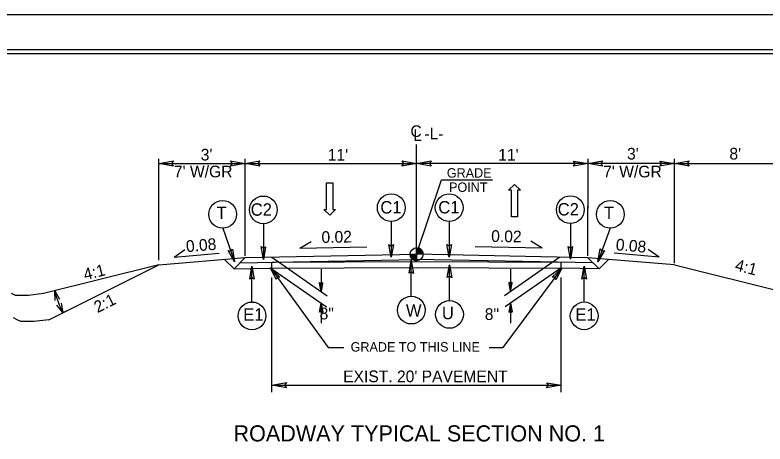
# Model space of a CAD drawing. Extents: x 573711 to 575883, y -54585 to -53485.
# Drawn here: x 574438.9 to 574921.1, y -53761 to -53485 of the extents above; entities that cross this region are included whole.
import ezdxf

# ---------------------------------------------------------------- set-up
doc = ezdxf.new("R2010")
doc.units = 0
for name, color, linetype in [('Old_Level_1', 7, 'Continuous'), ('Old_Level_11', 7, 'Continuous'), ('Old_Level_2', 7, 'Continuous'), ('Old_Level_20', 7, 'Continuous'), ('Old_Level_3', 7, 'Continuous'), ('Prop Lane Arrow CELL', 7, 'Continuous'), ('Prop Terminator CELL', 7, 'Continuous'), ('Sheet Cutting Line CELL', 7, 'Continuous'), ('Sheet Plot Border Inside CELL', 7, 'Continuous'), ('Sheet Plot Border Outside CELL', 7, 'Continuous'), ('Sheet Typical CELL', 7, 'Continuous'), ('Typical Terminator CELL', 7, 'Continuous')]:
    doc.layers.add(name, color=color, linetype=linetype)

msp = doc.modelspace()

# ---------------------------------------------------------------- linework, layer by layer
at = {"layer": 'Old_Level_1'}
for p, q in [((574697.08, -53638.91), (574697.09, -53568.35)), ((574697.08, -53638.91), (574697.08, -53634.76)), ((574531.29, -53645.73), (574586.89, -53641.11)), ((574573.62, -53642.21), (574579.7, -53648.29)), ((574579.7, -53648.29), (574586.89, -53641.11)), ((574583.5, -53644.49), (574697.08, -53642.22)), ((574586.89, -53641.11), (574697.08, -53638.91)), ((574604.04, -53640.76), (574639.68, -53665.73)), ((574692.94, -53638.91), (574697.08, -53638.91)), ((574697.07, -53643.06), (574697.08, -53638.91)), ((574697.08, -53638.91), (574697.07, -53643.06)), ((574807.28, -53641.13), (574697.08, -53638.91)), ((574701.23, -53638.91), (574697.08, -53638.91)), ((574810.66, -53644.51), (574697.08, -53642.23)), ((574789.14, -53640.76), (574753.5, -53665.73)), ((574807.28, -53641.13), (574814.46, -53648.31)), ((574862.87, -53645.76), (574807.28, -53641.13)), ((574814.46, -53648.31), (574820.54, -53642.23)), ((574531.29, -53645.73), (574457.17, -53664.25)), ((574460.68, -53681.03), (574531.29, -53645.73)), ((574604.04, -53644.08), (574697.08, -53643.68)), ((574604.04, -53647.8), (574604.04, -53644.08)), ((574604.04, -53647.8), (574697.08, -53647.4)), ((574697.08, -53643.68), (574790.14, -53644.1)), ((574697.08, -53647.4), (574790.14, -53647.82)), ((574790.14, -53647.82), (574790.14, -53644.1)), ((574862.87, -53645.76), (574936.99, -53664.3)), ((574579.7, -53648.29), (574604.04, -53647.8)), ((574603.43, -53647.82), (574639.07, -53672.77)), ((574635.69, -53648.49), (574635.69, -53662.93)), ((574789.74, -53647.82), (574754.11, -53672.77)), ((574757.48, -53648.49), (574757.48, -53662.93)), ((574814.46, -53648.31), (574790.14, -53647.82)), ((574635.69, -53662.93), (574634.72, -53657.41)), ((574635.69, -53658.12), (574634.72, -53657.41)), ((574635.69, -53662.93), (574635.41, -53657.92)), ((574635.69, -53662.93), (574636.67, -53657.41)), ((574636.67, -53657.41), (574635.69, -53658.12)), ((574636.52, -53657.51), (574635.69, -53662.93)), ((574757.48, -53662.93), (574756.51, -53657.41)), ((574756.51, -53657.41), (574757.48, -53658.12)), ((574756.66, -53657.51), (574757.48, -53662.93)), ((574757.48, -53662.93), (574758.46, -53657.41)), ((574757.48, -53662.93), (574757.77, -53657.92)), ((574635.69, -53670.41), (574634.72, -53675.93)), ((574635.69, -53670.41), (574635.69, -53683.33)), ((574635.69, -53670.41), (574636.67, -53675.93)), ((574757.49, -53670.41), (574756.51, -53675.93)), ((574757.49, -53670.41), (574757.49, -53683.33)), ((574757.49, -53670.41), (574758.46, -53675.93)), ((574634.72, -53675.93), (574635.69, -53675.22)), ((574635.69, -53675.22), (574636.67, -53675.93)), ((574757.49, -53675.22), (574756.51, -53675.93))]:
    msp.add_line(p, q, dxfattribs=at)
for points in [[(574697.12, -53634.76), (574697.12, -53634.76), (574697.12, -53638.91)], [(574697.2, -53634.76), (574697.2, -53638.91)], [(574697.29, -53634.77), (574697.29, -53638.91)], [(574697.37, -53634.77), (574697.37, -53638.91)], [(574697.45, -53634.78), (574697.45, -53638.91)], [(574697.54, -53634.79), (574697.53, -53638.91)], [(574697.62, -53634.8), (574697.62, -53638.91)], [(574697.7, -53634.81), (574697.7, -53638.91)], [(574697.78, -53634.82), (574697.78, -53638.91)], [(574697.87, -53634.84), (574697.87, -53638.91)], [(574697.95, -53634.86), (574697.95, -53638.91)], [(574698.03, -53634.87), (574698.03, -53638.91)], [(574698.12, -53634.89), (574698.12, -53638.91)], [(574698.2, -53634.92), (574698.2, -53638.91)], [(574698.28, -53634.94), (574698.28, -53638.91)], [(574698.36, -53634.97), (574698.36, -53638.91)], [(574698.45, -53634.99), (574698.45, -53638.91)], [(574698.53, -53635.02), (574698.53, -53638.91)], [(574698.61, -53635.06), (574698.61, -53638.91)], [(574698.7, -53635.1), (574698.7, -53638.91)], [(574698.78, -53635.13), (574698.78, -53638.91)], [(574698.86, -53635.17), (574698.86, -53638.91)], [(574698.95, -53635.21), (574698.95, -53638.91)], [(574699.03, -53635.25), (574699.03, -53638.91)], [(574699.11, -53635.3), (574699.11, -53638.91)], [(574699.19, -53635.34), (574699.19, -53638.91)], [(574699.28, -53635.39), (574699.28, -53638.91)], [(574699.36, -53635.45), (574699.36, -53638.91)], [(574699.44, -53635.5), (574699.44, -53638.91)], [(574699.53, -53635.57), (574699.53, -53638.91)], [(574699.61, -53635.62), (574699.61, -53638.91)], [(574699.69, -53635.69), (574699.69, -53638.91)], [(574699.77, -53635.76), (574699.77, -53638.91)], [(574699.86, -53635.83), (574699.86, -53638.91)], [(574699.94, -53635.91), (574699.94, -53638.91)], [(574700.02, -53635.99), (574700.02, -53638.91)], [(574700.11, -53636.07), (574700.11, -53638.91)], [(574700.19, -53636.17), (574700.19, -53638.91)], [(574700.27, -53636.27), (574700.27, -53638.91)], [(574700.36, -53636.37), (574700.36, -53638.91)], [(574700.44, -53636.48), (574700.44, -53638.91)], [(574700.52, -53636.6), (574700.52, -53638.91)], [(574700.6, -53636.73), (574700.6, -53638.91)], [(574700.69, -53636.87), (574700.69, -53638.91)], [(574700.77, -53637.01), (574700.77, -53638.91)], [(574700.85, -53637.19), (574700.85, -53638.91)], [(574700.94, -53637.38), (574700.94, -53638.91)], [(574701.02, -53637.61), (574701.02, -53638.91)], [(574701.1, -53637.9), (574701.1, -53638.91)], [(574692.95, -53638.91), (574692.95, -53639.36)], [(574693.04, -53638.91), (574693.04, -53639.85)], [(574693.12, -53638.91), (574693.12, -53640.15)], [(574693.2, -53638.91), (574693.2, -53640.4)], [(574693.29, -53638.91), (574693.29, -53640.59)], [(574693.37, -53638.91), (574693.37, -53640.76)], [(574693.45, -53638.91), (574693.45, -53640.92)], [(574693.53, -53638.91), (574693.53, -53641.07)], [(574693.62, -53638.91), (574693.62, -53641.2)], [(574693.7, -53638.91), (574693.7, -53641.32)], [(574693.78, -53638.91), (574693.78, -53641.43)], [(574693.87, -53638.91), (574693.87, -53641.53)], [(574693.95, -53638.91), (574693.95, -53641.63)], [(574694.03, -53638.91), (574694.03, -53641.72)], [(574694.11, -53638.91), (574694.11, -53641.81)], [(574694.2, -53638.91), (574694.2, -53641.9)], [(574694.28, -53638.91), (574694.28, -53641.97)], [(574694.36, -53638.91), (574694.36, -53642.05)], [(574694.45, -53638.91), (574694.45, -53642.12)], [(574694.53, -53638.91), (574694.53, -53642.18)], [(574694.61, -53638.91), (574694.61, -53642.25)], [(574694.7, -53638.91), (574694.7, -53642.3)], [(574694.78, -53638.91), (574694.78, -53642.36)], [(574694.86, -53638.91), (574694.86, -53642.41)], [(574694.94, -53638.91), (574694.94, -53642.47)], [(574695.03, -53638.91), (574695.03, -53642.52)], [(574695.11, -53638.91), (574695.11, -53642.56)], [(574695.19, -53638.91), (574695.19, -53642.61)], [(574695.28, -53638.91), (574695.28, -53642.64)], [(574695.36, -53638.91), (574695.36, -53642.68)], [(574695.44, -53638.91), (574695.44, -53642.72)], [(574695.53, -53638.91), (574695.52, -53642.76)], [(574695.61, -53638.91), (574695.61, -53642.79)], [(574695.69, -53638.91), (574695.69, -53642.82)], [(574695.77, -53638.91), (574695.77, -53642.85)], [(574695.86, -53638.91), (574695.86, -53642.88)], [(574695.94, -53638.91), (574695.94, -53642.89)], [(574696.02, -53638.91), (574696.02, -53642.92)], [(574696.11, -53638.91), (574696.11, -53642.94)], [(574696.19, -53638.91), (574696.19, -53642.96)], [(574696.27, -53638.91), (574696.27, -53642.98)], [(574696.35, -53638.91), (574696.35, -53643)], [(574696.44, -53638.91), (574696.44, -53643)], [(574696.52, -53638.91), (574696.52, -53643.02)], [(574696.6, -53638.91), (574696.6, -53643.03)], [(574696.69, -53638.91), (574696.69, -53643.04)], [(574696.77, -53638.91), (574696.77, -53643.05)], [(574696.85, -53638.91), (574696.85, -53643.05)], [(574696.94, -53638.91), (574696.94, -53643.06)], [(574697.02, -53638.91), (574697.02, -53643.06), (574697.02, -53643.06)], [(574701.19, -53638.32), (574701.18, -53638.91)], [(574457.17, -53664.25), (574447.55, -53665.45), (574445.15, -53665.45), (574441.54, -53665.45), (574439.14, -53665.45), (574436.74, -53664.26)], [(574460.68, -53681.03), (574451.07, -53682.23), (574448.66, -53682.23), (574445.05, -53682.23), (574442.65, -53682.23), (574440.25, -53681.03), (574437.84, -53679.83)]]:
    msp.add_lwpolyline(points, dxfattribs=at)
msp.add_circle((574697.08, -53638.91), 4.15, dxfattribs=at)
for start, end in [(359.9851, 89.9851), (179.9851, 269.9851)]:
    msp.add_arc((574697.08, -53638.91), 4.15, start, end, dxfattribs=at)
at = {"layer": 'Old_Level_11'}
for p, q in [((574531.29, -53642.73), (574531.3, -53577.53)), ((574531.29, -53642.73), (574531.3, -53577.53)), ((574586.89, -53638.1), (574586.89, -53577.54)), ((574586.89, -53638.1), (574586.89, -53577.54)), ((574586.89, -53639.9), (574586.89, -53578.86)), ((574807.28, -53638.13), (574807.29, -53577.56)), ((574807.28, -53638.13), (574807.29, -53577.56)), ((574807.28, -53639.92), (574807.29, -53578.88)), ((574807.28, -53639.92), (574807.29, -53579.3)), ((574862.87, -53642.76), (574862.88, -53577.56)), ((574862.87, -53642.76), (574862.88, -53577.56)), ((574862.87, -53644.56), (574862.88, -53579.3)), ((574531.3, -53580.53), (574586.89, -53580.54)), ((574586.89, -53580.54), (574697.09, -53580.55)), ((574807.29, -53580.56), (574697.09, -53580.55)), ((574862.88, -53580.56), (574807.29, -53580.56)), ((574862.88, -53580.56), (574937, -53580.57)), ((574680.78, -53617.84), (574680.78, -53640.87)), ((574718.04, -53617.81), (574718.04, -53640.84)), ((574572.45, -53622.13), (574580.12, -53643.85)), ((574598.59, -53619.27), (574598.59, -53642.3)), ((574795.96, -53619.11), (574795.96, -53642.14)), ((574821.59, -53622.16), (574813.65, -53643.78)), ((574591.26, -53669.65), (574591.26, -53646.62)), ((574693.68, -53665.94), (574693.68, -53642.91)), ((574718.23, -53668.73), (574718.23, -53645.7)), ((574804.83, -53669.62), (574804.83, -53646.59)), ((574604.03, -53727.6), (574604.03, -53653.86)), ((574790.13, -53727.62), (574790.14, -53653.87)), ((574469.74, -53676.42), (574472.33, -53675.13)), ((574604.03, -53723.13), (574790.13, -53723.15))]:
    msp.add_line(p, q, dxfattribs=at)
for points in [[(574682.2, -53632.62), (574680.78, -53640.87), (574679.31, -53632.58), (574680.78, -53633.63)], [(574719.46, -53632.59), (574718.04, -53640.84), (574716.57, -53632.54), (574718.04, -53633.6)], [(574578.72, -53635.6), (574580.12, -53643.85), (574575.98, -53636.52), (574577.71, -53637.02)], [(574600.01, -53634.05), (574598.59, -53642.3), (574597.12, -53634), (574598.59, -53635.06)], [(574797.38, -53633.89), (574795.96, -53642.14), (574794.49, -53633.85), (574795.96, -53634.9)], [(574817.83, -53636.53), (574813.65, -53643.78), (574815.13, -53635.49), (574816.15, -53636.99)], [(574589.84, -53654.87), (574591.26, -53646.62), (574592.73, -53654.92), (574591.26, -53653.86)], [(574606.83, -53655.2), (574603.16, -53647.67), (574609.2, -53653.55), (574607.39, -53653.55)], [(574692.25, -53651.16), (574693.68, -53642.91), (574695.14, -53651.21), (574693.68, -53650.15)], [(574716.81, -53653.95), (574718.23, -53645.7), (574719.7, -53654), (574718.23, -53652.94)], [(574803.41, -53654.84), (574804.83, -53646.59), (574806.3, -53654.89), (574804.83, -53653.84)], [(574784.31, -53653.67), (574790.37, -53647.9), (574786.6, -53655.43), (574786.05, -53653.71)]]:
    msp.add_lwpolyline(points, close=True, dxfattribs=at)
for points in [[(574464.7, -53668.64), (574464.42, -53662.46), (574467.57, -53667.78)], [(574468.56, -53670.38), (574469.65, -53676.47), (574465.82, -53671.61)]]:
    msp.add_lwpolyline(points, dxfattribs=at)
for centre in [(574572.45, -53613.22), (574598.59, -53610.36), (574680.78, -53608.93), (574718.04, -53608.9), (574795.96, -53610.2), (574821.59, -53613.25), (574693.68, -53674.85), (574591.26, -53678.56), (574718.23, -53677.64), (574804.83, -53678.53)]:
    msp.add_circle(centre, 8.91, dxfattribs=at)
msp.add_arc((574531.09, -53645.65), 68.74, 194.187, 206.6371, dxfattribs=at)
at = {"layer": 'Old_Level_2'}
for p, q in [((574621.95, -53635.08), (574629.2, -53630.7)), ((574777.89, -53634.95), (574770.63, -53630.57)), ((574541.18, -53640.71), (574548.12, -53635.85)), ((574621.95, -53635.08), (574665.13, -53634.22)), ((574777.89, -53634.95), (574734.7, -53634.08)), ((574853, -53640.71), (574846.06, -53635.85)), ((574541.18, -53640.71), (574570.08, -53638.17)), ((574853, -53640.71), (574824.1, -53638.17))]:
    msp.add_line(p, q, dxfattribs=at)
at = {"layer": 'Old_Level_3'}
for p, q in [((574697.08, -53638.91), (574713.15, -53591.07)), ((574713.15, -53591.07), (574745.94, -53591.07)), ((574603.16, -53647.67), (574640.24, -53698.95)), ((574790.37, -53647.9), (574752.57, -53698.95)), ((574640.24, -53698.95), (574650.21, -53698.95)), ((574743.69, -53698.95), (574752.57, -53698.95))]:
    msp.add_line(p, q, dxfattribs=at)
at = {"layer": 'Prop Lane Arrow CELL'}
for p, q in [((574639.21, -53610.04), (574639.21, -53593.03)), ((574639.21, -53593.03), (574643.22, -53593.03)), ((574643.22, -53593.03), (574643.22, -53610.04)), ((574756.21, -53597.79), (574759.98, -53593.96)), ((574759.98, -53593.96), (574763.87, -53597.79)), ((574758.03, -53597.79), (574756.21, -53597.79)), ((574758.03, -53614.8), (574758.03, -53597.79)), ((574763.87, -53597.79), (574762.04, -53597.79)), ((574762.04, -53597.79), (574762.04, -53614.8)), ((574641.28, -53613.86), (574637.39, -53610.04)), ((574637.39, -53610.04), (574639.21, -53610.04)), ((574645.04, -53610.04), (574641.28, -53613.86)), ((574643.22, -53610.04), (574645.04, -53610.04)), ((574762.04, -53614.8), (574758.03, -53614.8))]:
    msp.add_line(p, q, dxfattribs=at)
at = {"layer": 'Prop Terminator CELL'}
for points in [[(574636.69, -53657.15), (574635.69, -53662.93), (574634.66, -53657.11), (574635.69, -53657.85)], [(574756.49, -53657.15), (574757.48, -53662.93), (574758.51, -53657.11), (574757.48, -53657.85)], [(574634.7, -53676.19), (574635.69, -53670.41), (574636.72, -53676.23), (574635.69, -53675.49)], [(574758.48, -53676.19), (574757.49, -53670.41), (574756.46, -53676.23), (574757.49, -53675.49)]]:
    msp.add_lwpolyline(points, close=True, dxfattribs=at)
at = {"layer": 'Sheet Cutting Line CELL'}
msp.add_line((575395.13, -53485.01), (573711.13, -53485.01), dxfattribs=at)
at = {"layer": 'Sheet Plot Border Inside CELL'}
msp.add_lwpolyline([(575390.63, -53507.46), (573724.13, -53507.46), (573724.13, -54562.56), (575390.63, -54562.56)], close=True, dxfattribs=at)
at = {"layer": 'Sheet Plot Border Outside CELL'}
msp.add_lwpolyline([(575395.13, -53485.01), (573711.13, -53485.01), (573711.13, -54585.01), (575395.13, -54585.01)], close=True, dxfattribs=at)
at = {"layer": 'Sheet Typical CELL'}
msp.add_lwpolyline([(575378.13, -53510.01), (573878.13, -53510.01), (573878.13, -54560.01), (575378.13, -54560.01)], close=True, dxfattribs=at)
at = {"layer": 'Typical Terminator CELL'}
for points in [[(574540.67, -53582.15), (574531.3, -53580.53), (574540.72, -53578.87), (574539.53, -53580.53)], [(574577.52, -53578.92), (574586.89, -53580.54), (574577.47, -53582.2), (574578.66, -53580.54)], [(574596.26, -53582.15), (574586.89, -53580.54), (574596.32, -53578.87), (574595.12, -53580.54)], [(574687.71, -53578.93), (574697.09, -53580.55), (574687.66, -53582.21), (574688.86, -53580.55)], [(574706.46, -53582.16), (574697.09, -53580.55), (574706.51, -53578.88), (574705.32, -53580.55)], [(574797.91, -53578.94), (574807.29, -53580.56), (574797.86, -53582.23), (574799.06, -53580.56)], [(574816.66, -53582.17), (574807.29, -53580.56), (574816.71, -53578.89), (574815.51, -53580.56)], [(574853.51, -53578.95), (574862.88, -53580.56), (574853.45, -53582.23), (574854.65, -53580.56)], [(574872.25, -53582.18), (574862.88, -53580.56), (574872.3, -53578.9), (574871.11, -53580.56)], [(574613.41, -53724.75), (574604.04, -53723.13), (574613.46, -53721.47), (574612.26, -53723.13)], [(574780.76, -53721.54), (574790.13, -53723.15), (574780.7, -53724.82), (574781.9, -53723.15)]]:
    msp.add_lwpolyline(points, close=True, dxfattribs=at)

# ---------------------------------------------------------------- texts
at = {"layer": 'Old_Level_1'}
for s, rotation, p in [('4:1', 345.9584, (574901.31, -53649.21)), ('4:1', 14.0309, (574483.95, -53655.73)), ('2:1', 26.5607, (574492, -53676.78)), (' 8" ', 360, (574738.12, -53681.17))]:
    msp.add_text(s, height=7.513, rotation=rotation, dxfattribs=at).set_placement(p)
msp.add_text(' 8" ', height=7.513, dxfattribs=at).set_placement((574631.95, -53680.81))
at = {"layer": 'Old_Level_11'}
for s, height, rotation, p in [('C', 7.51, 359.9946, (574693.11, -53563.51)), ('L', 7.51, 359.9415, (574694.98, -53566.04)), ('-L-', 7.513, 359.9946, (574702.12, -53565.01)), ("3'", 7.513, 359.9946, (574832.37, -53578)), ("8'", 7.513, 359.9946, (574898.18, -53578)), ("3'", 7.513, 359.9946, (574558.29, -53578.61)), ("11'", 7.513, 359.9946, (574640.01, -53578.62)), ("11'", 7.513, 359.9946, (574749.57, -53578.63)), ("7' W/GR", 7.513, 359.9946, (574541.07, -53589.44)), ("7' W/GR", 7.513, 359.9946, (574817.05, -53589.47)), ("EXIST. 20' PAVEMENT", 7.513, 359.9946, (574649.87, -53721.21))]:
    msp.add_text(s, height=height, rotation=rotation, dxfattribs=at).set_placement(p)
at = {"layer": 'Old_Level_20'}
for s, height, p in [('T', 7.98, (574568.44, -53616.28)), ('C2', 7.977, (574590.43, -53614.12)), ('C1', 7.977, (574673.78, -53612.7)), ('C1', 7.977, (574711.03, -53612.66)), ('C2', 7.977, (574787.8, -53613.97)), ('T', 7.98, (574817.57, -53616.31)), ('W', 7.98, (574690.22, -53679.02)), ('E1', 7.977, (574585.63, -53681.62)), ('U', 7.98, (574713.36, -53680.7)), ('E1', 7.977, (574799.21, -53681.59))]:
    msp.add_text(s, height=height, dxfattribs=at).set_placement(p)
at = {"layer": 'Old_Level_3'}
for s, height, rotation, p in [('GRADE', 6.046, 359.9946, (574716.52, -53589.62)), ('POINT', 6.046, 359.9946, (574717.98, -53598.78)), ('0.02 ', 7.513, 358.8489, (574744.98, -53630.92)), ('0.02 ', 7.513, 1.1404, (574636.01, -53631.69)), ('0.08', 7.513, 4.7561, (574549.11, -53637.58)), ('0.08', 7.513, 355.2332, (574824.92, -53636.31)), ('ROADWAY TYPICAL SECTION NO. 1', 10.3693, 359.9946, (574579.38, -53759.32))]:
    msp.add_text(s, height=height, rotation=rotation, dxfattribs=at).set_placement(p)
msp.add_text('GRADE TO THIS LINE', height=6.0464, dxfattribs=at).set_placement((574654.68, -53701.5))

doc.saveas('drawing.dxf')
